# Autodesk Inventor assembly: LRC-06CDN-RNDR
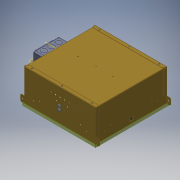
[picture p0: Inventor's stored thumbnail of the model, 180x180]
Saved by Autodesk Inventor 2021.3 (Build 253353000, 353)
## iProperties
Part Number: LRC-06CDN-RNDR
Document SubType Name: Assembly
Designer: JChurch
Author: JChurch
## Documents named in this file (6)
- X:\Revit Files\0000-Un-Zipped\COB\LRC-06CDN-RND\LRC-06CDN-RNDR.iam
- X:\INVENTOR\830\830399-00-00.ipt
- X:\INVENTOR\830\830455-00-38.ipt
- X:\INVENTOR\881\881088-00-00.iam
- X:\INVENTOR\KIRLIN_ENG\750\750043-00-XX.iam
- X:\INVENTOR\KIRLIN_ENG\725\725075-00-00.ipt
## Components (5 placed, 5 different names)
1. 830399-00-00:1 — Mate:2, Mate:3, Mate:6, Tangent:1, Angle:1
2. 830455-00-38:1 — Mate:4, Mate:5, Flush:1, Mate:6, Mate:7, Insert:2
3. 881088-00-00:1 [sub-assembly] — Tangent:1, Mate:7, Angle:1
4. 750043-00-XX:1 [sub-assembly] — Insert:1, Insert:2
5. 725075-00-00:1 — Insert:1
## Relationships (11: Mate 6, Insert 2, Flush 1, Tangent 1, Angle 1)
- Mate:2: 830399-00-00:1
- Mate:3: 830399-00-00:1
- Mate:4: 830455-00-38:1
- Mate:5: 830455-00-38:1
- Flush:1: 830455-00-38:1
- Mate:6: 830399-00-00:1 ↔ 830455-00-38:1
- Tangent:1: 830399-00-00:1 ↔ 881088-00-00:1
- Mate:7: 830455-00-38:1 ↔ 881088-00-00:1
- Angle:1: 830399-00-00:1 ↔ 881088-00-00:1
- Insert:1: 750043-00-XX:1 ↔ 725075-00-00:1
- Insert:2: 830455-00-38:1 ↔ 750043-00-XX:1
